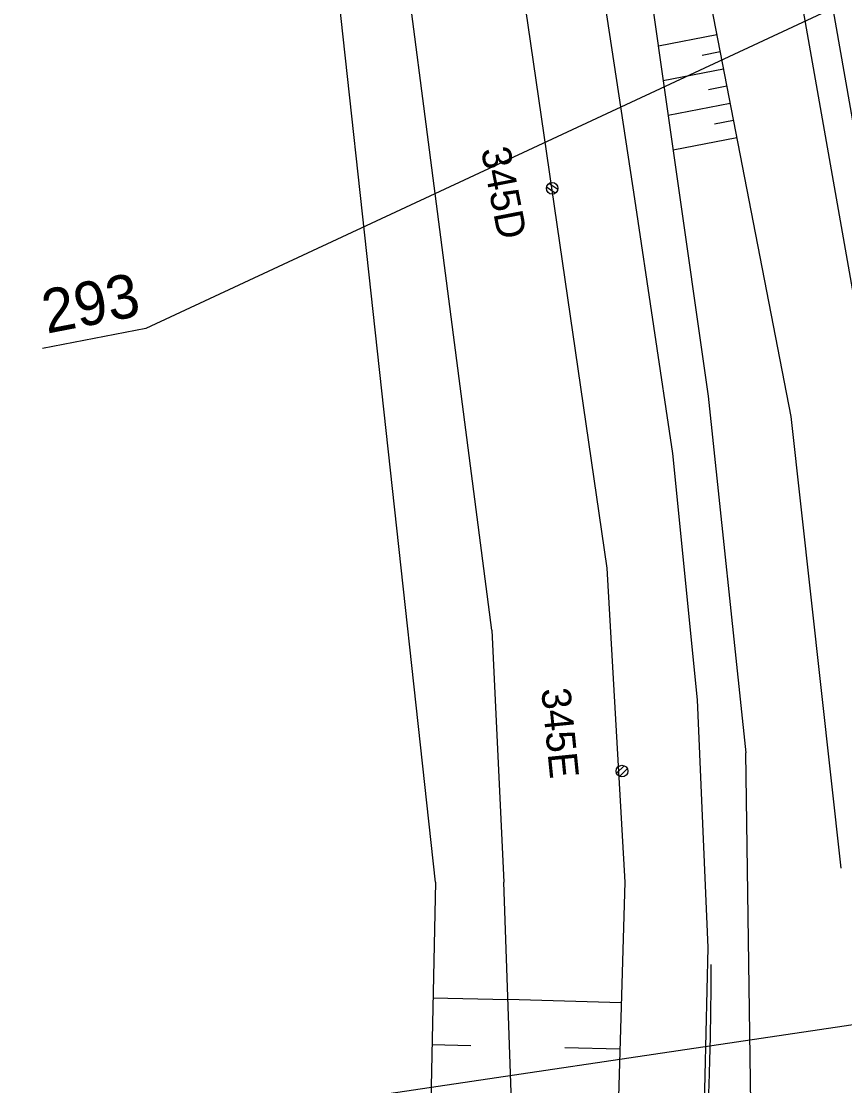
# Model space of a CAD drawing. Extents: x -545846 to -545044, y -1122650 to -1119108.
# Drawn here: x -545674.1 to -545638.75, y -1119708.74 to -1119663.02 of the extents above; entities that cross this region are included whole.
import ezdxf

# ---------------------------------------------------------------- set-up
doc = ezdxf.new("R2010")
doc.units = 0
for name, color, linetype in [('so180602', 7, 'Continuous'), ('Vrstva 1 - Koleje', 7, 'Continuous'), ('Vrstva 11', 7, 'Continuous'), ('Vrstva 35', 7, 'Continuous'), ('Vrstva 44', 7, 'Continuous'), ('Vrstva 48', 7, 'Continuous'), ('Vrstva 49', 7, 'Continuous'), ('Vrstva 62', 7, 'Continuous'), ('Vrstva 63', 7, 'Continuous')]:
    doc.layers.add(name, color=color, linetype=linetype)

msp = doc.modelspace()

# ---------------------------------------------------------------- linework, layer by layer
at = {"layer": 'Vrstva 1 - Koleje'}
msp.add_lwpolyline([(-545673.811, -1119482.836), (-545671.313, -1119495.675), (-545669.505, -1119504.975), (-545667.947, -1119513.018), (-545662.4, -1119541.424), (-545660.697, -1119551.332), (-545659.275, -1119561.505), (-545658.148, -1119572.104), (-545657.527, -1119582.463), (-545657.339, -1119589.06), (-545656.945, -1119598.604), (-545656.274, -1119608.583), (-545655.31, -1119618.93), (-545654.021, -1119629.341), (-545652.534, -1119639.322), (-545651.124, -1119648.586), (-545649.453, -1119659.616), (-545647.771, -1119670.646), (-545646.146, -1119681.578), (-545645.086, -1119692.159), (-545644.623, -1119702.795), (-545644.886, -1119713.798)], dxfattribs=at)
at = {"layer": 'Vrstva 11'}
for p, q in [((-545651.177, -1119670.399), (-545651.555, -1119670.144)), ((-545651.069, -1119670.245), (-545651.453, -1119669.986)), ((-545648.544, -1119695.314), (-545648.221, -1119694.991)), ((-545648.414, -1119695.449), (-545648.087, -1119695.122))]:
    msp.add_line(p, q, dxfattribs=at)
for centre in [(-545651.311, -1119670.19), (-545648.314, -1119695.222)]:
    msp.add_circle(centre, 0.25, dxfattribs=at)
at = {"layer": 'Vrstva 35'}
msp.add_line((-545634.944, -1119687.133), (-545642.159, -1119645.823), dxfattribs=at)
at = {"layer": 'Vrstva 44'}
msp.add_lwpolyline([(-545654.9, -1119582.222), (-545645.965, -1119631.818), (-545637.145, -1119681.816), (-545629.836, -1119730.566), (-545626.416, -1119761.521), (-545622.849, -1119813.009), (-545619.592, -1119863.304), (-545618.858, -1119914.175), (-545618.881, -1119950.565), (-545618.715, -1119963.415), (-545629.02, -1119997.179)], dxfattribs=at)
at = {"layer": 'Vrstva 48'}
for p, q in [((-545644.249, -1119663.598), (-545646.753, -1119664.085)), ((-545644.106, -1119664.334), (-545644.868, -1119664.482)), ((-545643.962, -1119665.07), (-545646.541, -1119665.571)), ((-545643.819, -1119665.806), (-545644.604, -1119665.959)), ((-545643.676, -1119666.543), (-545646.329, -1119667.058)), ((-545643.533, -1119667.279), (-545644.34, -1119667.436)), ((-545643.39, -1119668.015), (-545646.117, -1119668.545))]:
    msp.add_line(p, q, dxfattribs=at)
at = {"layer": 'Vrstva 49'}
for points in [[(-545655.117, -1119579.257), (-545655.465, -1119586.681), (-545654.728, -1119601.362), (-545652.589, -1119621.359), (-545650.163, -1119640.071), (-545647.474, -1119659.033), (-545644.608, -1119679.124), (-545643.003, -1119694.436)], [(-545655.117, -1119579.257), (-545654.637, -1119587.147), (-545653.079, -1119601.278), (-545650.95, -1119621.407), (-545647.998, -1119639.764), (-545644.487, -1119662.372), (-545641.063, -1119679.985), (-545638.92, -1119699.386)]]:
    msp.add_lwpolyline(points, dxfattribs=at)
at = {"layer": 'Vrstva 62'}
for points in [[(-545656.326, -1119699.999), (-545660.928, -1119657.766), (-545665.632, -1119629.539)], [(-545653.904, -1119689.166), (-545660.218, -1119640.504), (-545661.63, -1119631.691)], [(-545657.384, -1119632.351), (-545652.8, -1119660.112), (-545648.962, -1119686.501), (-545648.197, -1119699.999)], [(-545653.904, -1119689.166), (-545653.904, -1119689.166), (-545653.383, -1119700)], [(-545642.712, -1119714.53), (-545643.003, -1119694.436)], [(-545656.326, -1119699.999), (-545656.734, -1119719.569), (-545658.021, -1119735.223), (-545653.481, -1119739.41)], [(-545653.017, -1119735.395), (-545654.895, -1119731.229), (-545653.499, -1119723.26), (-545652.925, -1119713.134), (-545653.383, -1119700)], [(-545648.197, -1119699.999), (-545648.722, -1119717.969), (-545650.953, -1119731.732)], [(-545656.43, -1119704.968), (-545653.208, -1119705.035)], [(-545648.348, -1119705.173), (-545653.208, -1119705.031)], [(-545656.471, -1119706.968), (-545654.805, -1119707.003)], [(-545648.406, -1119707.173), (-545650.772, -1119707.104)]]:
    msp.add_lwpolyline(points, dxfattribs=at)
msp.add_arc((-545814.75, -1119703.119), 170.27, 337.66582, 359.86231, dxfattribs=at)
at = {"layer": 'Vrstva 63'}
for p, q in [((-545584.143, -1119636.743), (-545668.751, -1119676.21)), ((-545668.751, -1119676.21), (-545673.195, -1119677.074)), ((-545629.158, -1119704.744), (-545685.803, -1119713.163))]:
    msp.add_line(p, q, dxfattribs=at)

# ---------------------------------------------------------------- texts
at = {"layer": 'so180602'}
msp.add_text('293', height=1.875, rotation=10.9955, dxfattribs=at).set_placement((-545673.007, -1119676.438))
at = {"layer": 'Vrstva 11'}
for s, rotation, p in [('345D', 281.0564, (-545654.372, -1119668.532)), ('345E', 275.7106, (-545651.783, -1119691.701))]:
    msp.add_text(s, height=1.25, rotation=rotation, dxfattribs=at).set_placement(p)

doc.saveas('drawing.dxf')
